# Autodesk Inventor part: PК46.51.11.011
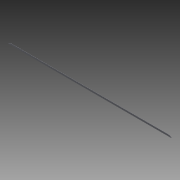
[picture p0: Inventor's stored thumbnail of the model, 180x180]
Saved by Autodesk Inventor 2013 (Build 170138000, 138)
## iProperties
Shininess: 64.0
Length Units: 11269
Angle Units: 11279
Time Units: 11290
Mass Units: 11283
Length Display Precision: 3
Angle Display Precision: 2
Compacted: True
Part Number: PК46.51.11.011
Document SubType Name: Листовой материал
Created: 2004-12
Material: Steel, Mild
Designer: =<Author>
Manufacturer: Standard
Standards Organization: Custom
Description: strip seal
Density: 7.86 g/cm^3
Sheet Metal Rule: По умолчанию
Mass: 345.925 g
Surface Area: 499.704 cm^2
Volume: 44.0109 cm^3
Density: 0.0
Volumn: 0.0
Area: 0.0
PropertySet Name: Model Information
Control State: 0
Master: False
Checked Out: False
Checked Out Date: 2008-10-15
Last Check In Date: 2008-10-15
Author: PVitaliy
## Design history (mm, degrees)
node "ФлнОтгиб1"
feature "Вырез1" dims "d11" = 2 (= Толщина), "d12" = 0
body "Solid1"
sketch "Эскиз1"
  geometry: L1 (0, 0)-(1496, 0)
  constraints: 2 end point, 1 horizontal, 1 other
  dimensions: "d0" = 1496 distance of L1.start L1.end
feature "Пластина1" dims "d2" = 15, "d3" = 2 (= Ширина_просечки), "d5" = 4 (= Минимальный_остаток), "d7" = 2 (= Радиус_гибки), "d8" = 2, "Толщина" = 2
feature "Изгиб1" dims "d3" = 2 (= Ширина_просечки), "d4" = 1 (= Глубина_просечки), "d5" = 4 (= Минимальный_остаток), "d6" = 2 (= Радиус_гибки), "d7" = 2 (= Радиус_гибки), "d8" = 2, "Толщина" = 2, "Зазор_стыка" = 0.01
sketch "Эскиз2"
  geometry: L1 (1496, 15)-(0, 15) reference; L2 (0, 0)-(0, 15) reference; L3 (1496, 0)-(0, 0) reference; L4 (1496, 0)-(1496, 15) reference; A1 r 45 centre (30, -30) between (30, 15) and (0, 3.541); A2 r 45 centre (1451, -30) between (1484.541, 0) and (1451, 15)
  constraints: 4 point on circle, 4 point on line, 3 tangent, 2 centre point
  dimensions: "d9" = 90 diameter of A1; "d10" = 30 distance from line of A1.centre L2; "d13" = 90 diameter of A2
other parameters: "Радиус_гибки" = 2 (= Толщина), "Ширина_просечки" = 2 (= Толщина), "Глубина_просечки" = 1 (= 0.5 x Толщина), "Размер_высечки" = 8 (= 4 x Толщина), "Минимальный_остаток" = 4 (= 2 x Толщина), "Радиус_перехода" = 2 (= Радиус_гибки), "JacobiRadiusSize" = 2 (= Толщина), "GapSize" = 2 (= Толщина)
